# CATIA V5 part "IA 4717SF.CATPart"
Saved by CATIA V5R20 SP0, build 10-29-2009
Part number: IA 4717SF
Revision: ANY
Definition: UNKNOWN
Nomenclature: IA 4717SF
Source: Unknown
Bounding box of the stored display mesh (mm): x -2.35 to 2.35, y -7.925 to 9.045, z -2.35 to 2.35
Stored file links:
  C:\Users\Utente\Desktop\IO LAVORO\3D X SITO CF\CUMSA\3D files IA\IA 4717SF\IA 4717SF.CATPart
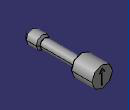
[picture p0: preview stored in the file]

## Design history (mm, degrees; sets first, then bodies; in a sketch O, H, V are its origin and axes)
Body1 "Cortar-Extruir2" (main body)
  Solid1: solid without history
